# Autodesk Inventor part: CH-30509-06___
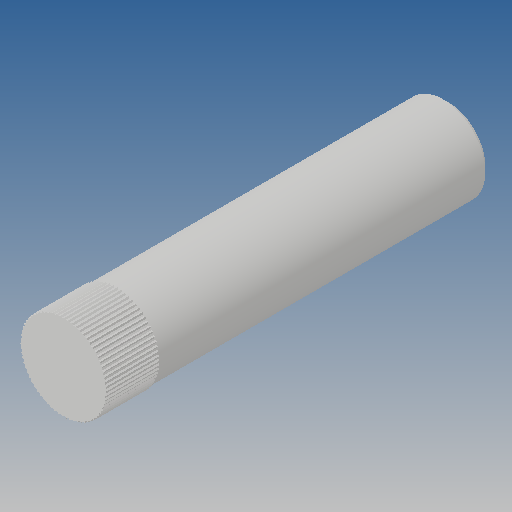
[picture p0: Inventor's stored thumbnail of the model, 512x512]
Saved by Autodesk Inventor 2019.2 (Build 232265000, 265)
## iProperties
Created: 2010-06
Part Number: CH-30509-06___
Material: Ogólny
Document SubType Name: Modeling
Designer: CADENGINEERING4
Density: 1 g/cm^3
Appearance: Domyślna
Author: CADENGINEERING4
Revision Number: ANY
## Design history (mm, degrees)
feature "NONE"
node "Bryła1"
